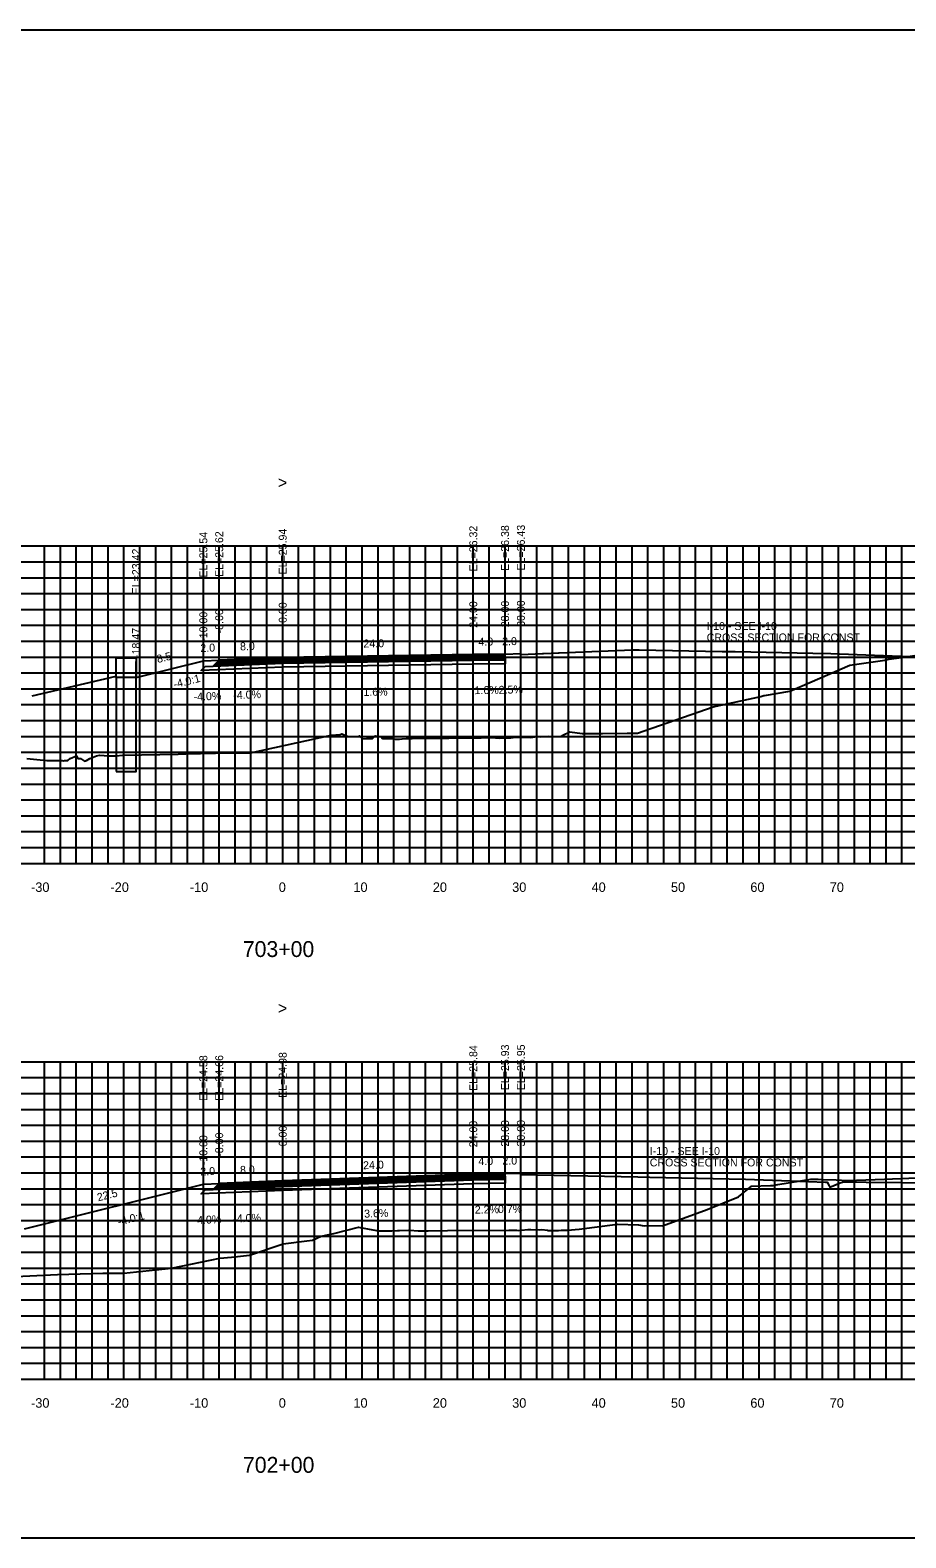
# Model space of a CAD drawing. Extents: x 1797518 to 1804843, y 248068 to 251132.
# Drawn here: x 1802599.2 to 1802709.5, y 250079.4 to 250269.4 of the extents above; entities that cross this region are included whole.
import ezdxf

# ---------------------------------------------------------------- set-up
doc = ezdxf.new("R2010")
doc.units = 0
for name, color, linetype in [('1', 7, 'Continuous'), ('10', 7, 'Continuous'), ('3', 7, 'Continuous'), ('4', 7, 'Continuous'), ('60', 7, 'Continuous'), ('BASE', 7, 'Continuous'), ('CL-CNST', 7, 'Continuous'), ('Level 62', 7, 'Continuous'), ('LOWER BINDER', 7, 'Continuous'), ('M-ROADS', 7, 'Continuous'), ('UPPER BINDER', 7, 'Continuous'), ('WEARING', 7, 'Continuous')]:
    doc.layers.add(name, color=color, linetype=linetype)

msp = doc.modelspace()

# ---------------------------------------------------------------- linework, layer by layer
for p, q in [((1802623, 250190.05), (1802623, 250192.05)), ((1802631, 250190.37), (1802631, 250192.37)), ((1802655, 250190.75), (1802655, 250192.75)), ((1802659, 250190.81), (1802659, 250192.81)), ((1802661, 250190.86), (1802661, 250192.86)), ((1802621, 250189.97), (1802621, 250191.97)), ((1802612.53, 250187.85), (1802612.53, 250189.85)), ((1802621, 250124.01), (1802621, 250126.01)), ((1802623, 250124.09), (1802623, 250126.09)), ((1802631, 250124.41), (1802631, 250126.41)), ((1802655, 250125.28), (1802655, 250127.28)), ((1802659, 250125.36), (1802659, 250127.36)), ((1802661, 250125.38), (1802661, 250127.38))]:
    msp.add_line(p, q)
msp.add_lwpolyline([(1802481, 250079.43), (1802781, 250079.43), (1802781, 250269.43), (1802481, 250269.43)], close=True)
at = {"layer": '3'}
msp.add_line((1802599.44, 250185.53), (1802610.03, 250188.01), dxfattribs=at)
at = {"layer": '60'}
for p, q in [((1802481, 250164.43), (1802781, 250164.43)), ((1802601, 250164.37), (1802601, 250164.43)), ((1802611, 250164.37), (1802611, 250164.43)), ((1802621, 250164.37), (1802621, 250164.43)), ((1802631, 250164.37), (1802631, 250164.43)), ((1802641, 250164.37), (1802641, 250164.43)), ((1802651, 250164.37), (1802651, 250164.43)), ((1802661, 250164.37), (1802661, 250164.43)), ((1802671, 250164.37), (1802671, 250164.43)), ((1802681, 250164.37), (1802681, 250164.43)), ((1802691, 250164.37), (1802691, 250164.43)), ((1802701, 250164.37), (1802701, 250164.43)), ((1802481, 250099.43), (1802781, 250099.43)), ((1802601, 250099.37), (1802601, 250099.43)), ((1802611, 250099.37), (1802611, 250099.43)), ((1802621, 250099.37), (1802621, 250099.43)), ((1802631, 250099.37), (1802631, 250099.43)), ((1802641, 250099.37), (1802641, 250099.43)), ((1802651, 250099.37), (1802651, 250099.43)), ((1802661, 250099.37), (1802661, 250099.43)), ((1802671, 250099.37), (1802671, 250099.43)), ((1802681, 250099.37), (1802681, 250099.43)), ((1802691, 250099.37), (1802691, 250099.43)), ((1802701, 250099.37), (1802701, 250099.43))]:
    msp.add_line(p, q, dxfattribs=at)
at = {"layer": 'BASE'}
for points in [[(1802621.25, 250189.26), (1802622.25, 250189.3), (1802631, 250189.65), (1802655, 250190.03), (1802659, 250190.09), (1802659, 250189.59), (1802655, 250189.53), (1802631, 250189.15), (1802620.73, 250188.74)], [(1802621.25, 250123.3), (1802622.25, 250123.34), (1802631, 250123.69), (1802655, 250124.56), (1802659, 250124.64), (1802659, 250124.14), (1802655, 250124.06), (1802631, 250123.19), (1802620.73, 250122.78)]]:
    msp.add_lwpolyline(points, close=True, dxfattribs=at)
at = {"layer": 'CL-CNST'}
for points in [[(1802612.53, 250187.85), (1802610.03, 250187.85), (1802610.03, 250190.35), (1802612.53, 250190.35)], [(1802610.03, 250175.99), (1802612.53, 250175.99), (1802612.53, 250187.85), (1802610.03, 250187.85)]]:
    msp.add_lwpolyline(points, close=True, dxfattribs=at)
for points in [[(1802612.53, 250187.85), (1802621, 250189.97), (1802623, 250190.05), (1802631, 250190.37), (1802655, 250190.75), (1802659, 250190.81), (1802661, 250190.86)], [(1802661, 250190.75), (1802663.71, 250190.86), (1802663.83, 250190.87), (1802665.75, 250190.95), (1802665.84, 250190.95), (1802675.04, 250191.33), (1802675.91, 250191.36), (1802686.34, 250191.15), (1802687.99, 250191.12), (1802697.79, 250190.92), (1802700.06, 250190.87), (1802707.78, 250190.58), (1802710.13, 250190.49)], [(1802598.49, 250118.38), (1802621, 250124.01), (1802623, 250124.09), (1802631, 250124.41), (1802655, 250125.28), (1802659, 250125.36), (1802661, 250125.38)], [(1802661, 250125.23), (1802675.73, 250124.92), (1802677.24, 250124.89), (1802687.23, 250124.69), (1802689.31, 250124.64), (1802697.22, 250124.34), (1802699.36, 250124.26), (1802699.53, 250124.25), (1802699.58, 250124.25), (1802699.83, 250123.78), (1802699.9, 250123.64), (1802701.23, 250124.15), (1802701.62, 250124.3), (1802704.47, 250124.27), (1802713.39, 250124.19)]]:
    msp.add_lwpolyline(points, dxfattribs=at)
at = {"layer": 'Level 62'}
for p, q in [((1802481, 250204.43), (1802781, 250204.43)), ((1802601, 250164.43), (1802601, 250204.43)), ((1802603, 250164.43), (1802603, 250204.43)), ((1802605, 250164.43), (1802605, 250204.43)), ((1802607, 250164.43), (1802607, 250204.43)), ((1802609, 250164.43), (1802609, 250204.43)), ((1802611, 250164.43), (1802611, 250204.43)), ((1802613, 250164.43), (1802613, 250204.43)), ((1802615, 250164.43), (1802615, 250204.43)), ((1802617, 250164.43), (1802617, 250204.43)), ((1802619, 250164.43), (1802619, 250204.43)), ((1802621, 250164.43), (1802621, 250204.43)), ((1802623, 250164.43), (1802623, 250204.43)), ((1802625, 250164.43), (1802625, 250204.43)), ((1802627, 250164.43), (1802627, 250204.43)), ((1802629, 250164.43), (1802629, 250204.43)), ((1802631, 250164.43), (1802631, 250204.43)), ((1802633, 250164.43), (1802633, 250204.43)), ((1802635, 250164.43), (1802635, 250204.43)), ((1802637, 250164.43), (1802637, 250204.43)), ((1802639, 250164.43), (1802639, 250204.43)), ((1802641, 250164.43), (1802641, 250204.43)), ((1802643, 250164.43), (1802643, 250204.43)), ((1802645, 250164.43), (1802645, 250204.43)), ((1802647, 250164.43), (1802647, 250204.43)), ((1802649, 250164.43), (1802649, 250204.43)), ((1802651, 250164.43), (1802651, 250204.43)), ((1802653, 250164.43), (1802653, 250204.43)), ((1802655, 250164.43), (1802655, 250204.43)), ((1802657, 250164.43), (1802657, 250204.43)), ((1802659, 250164.43), (1802659, 250204.43)), ((1802661, 250164.43), (1802661, 250204.43)), ((1802663, 250164.43), (1802663, 250204.43)), ((1802665, 250164.43), (1802665, 250204.43)), ((1802667, 250164.43), (1802667, 250204.43)), ((1802669, 250164.43), (1802669, 250204.43)), ((1802671, 250164.43), (1802671, 250204.43)), ((1802673, 250164.43), (1802673, 250204.43)), ((1802675, 250164.43), (1802675, 250204.43)), ((1802677, 250164.43), (1802677, 250204.43)), ((1802679, 250164.43), (1802679, 250204.43)), ((1802681, 250164.43), (1802681, 250204.43)), ((1802683, 250164.43), (1802683, 250204.43)), ((1802685, 250164.43), (1802685, 250204.43)), ((1802687, 250164.43), (1802687, 250204.43)), ((1802689, 250164.43), (1802689, 250204.43)), ((1802691, 250164.43), (1802691, 250204.43)), ((1802693, 250164.43), (1802693, 250204.43)), ((1802695, 250164.43), (1802695, 250204.43)), ((1802697, 250164.43), (1802697, 250204.43)), ((1802699, 250164.43), (1802699, 250204.43)), ((1802701, 250164.43), (1802701, 250204.43)), ((1802703, 250164.43), (1802703, 250204.43)), ((1802705, 250164.43), (1802705, 250204.43)), ((1802707, 250164.43), (1802707, 250204.43)), ((1802709, 250164.43), (1802709, 250204.43)), ((1802481, 250202.43), (1802781, 250202.43)), ((1802481, 250200.43), (1802781, 250200.43)), ((1802481, 250198.43), (1802781, 250198.43)), ((1802481, 250196.43), (1802781, 250196.43)), ((1802481, 250194.43), (1802781, 250194.43)), ((1802481, 250192.43), (1802781, 250192.43)), ((1802481, 250190.43), (1802781, 250190.43)), ((1802481, 250188.43), (1802781, 250188.43)), ((1802481, 250186.43), (1802781, 250186.43)), ((1802481, 250184.43), (1802781, 250184.43)), ((1802481, 250182.43), (1802781, 250182.43)), ((1802481, 250180.43), (1802781, 250180.43)), ((1802481, 250178.43), (1802781, 250178.43)), ((1802481, 250176.43), (1802781, 250176.43)), ((1802481, 250174.43), (1802781, 250174.43)), ((1802481, 250172.43), (1802781, 250172.43)), ((1802481, 250170.43), (1802781, 250170.43)), ((1802481, 250168.43), (1802781, 250168.43)), ((1802481, 250166.43), (1802781, 250166.43)), ((1802481, 250164.43), (1802781, 250164.43)), ((1802481, 250139.43), (1802781, 250139.43)), ((1802601, 250099.43), (1802601, 250139.43)), ((1802603, 250099.43), (1802603, 250139.43)), ((1802605, 250099.43), (1802605, 250139.43)), ((1802607, 250099.43), (1802607, 250139.43)), ((1802609, 250099.43), (1802609, 250139.43)), ((1802611, 250099.43), (1802611, 250139.43)), ((1802613, 250099.43), (1802613, 250139.43)), ((1802615, 250099.43), (1802615, 250139.43)), ((1802617, 250099.43), (1802617, 250139.43)), ((1802619, 250099.43), (1802619, 250139.43)), ((1802621, 250099.43), (1802621, 250139.43)), ((1802623, 250099.43), (1802623, 250139.43)), ((1802625, 250099.43), (1802625, 250139.43)), ((1802627, 250099.43), (1802627, 250139.43)), ((1802629, 250099.43), (1802629, 250139.43)), ((1802631, 250099.43), (1802631, 250139.43)), ((1802633, 250099.43), (1802633, 250139.43)), ((1802635, 250099.43), (1802635, 250139.43)), ((1802637, 250099.43), (1802637, 250139.43)), ((1802639, 250099.43), (1802639, 250139.43)), ((1802641, 250099.43), (1802641, 250139.43)), ((1802643, 250099.43), (1802643, 250139.43)), ((1802645, 250099.43), (1802645, 250139.43)), ((1802647, 250099.43), (1802647, 250139.43)), ((1802649, 250099.43), (1802649, 250139.43)), ((1802651, 250099.43), (1802651, 250139.43)), ((1802653, 250099.43), (1802653, 250139.43)), ((1802655, 250099.43), (1802655, 250139.43)), ((1802657, 250099.43), (1802657, 250139.43)), ((1802659, 250099.43), (1802659, 250139.43)), ((1802661, 250099.43), (1802661, 250139.43)), ((1802663, 250099.43), (1802663, 250139.43)), ((1802665, 250099.43), (1802665, 250139.43)), ((1802667, 250099.43), (1802667, 250139.43)), ((1802669, 250099.43), (1802669, 250139.43)), ((1802671, 250099.43), (1802671, 250139.43)), ((1802673, 250099.43), (1802673, 250139.43)), ((1802675, 250099.43), (1802675, 250139.43)), ((1802677, 250099.43), (1802677, 250139.43)), ((1802679, 250099.43), (1802679, 250139.43)), ((1802681, 250099.43), (1802681, 250139.43)), ((1802683, 250099.43), (1802683, 250139.43)), ((1802685, 250099.43), (1802685, 250139.43)), ((1802687, 250099.43), (1802687, 250139.43)), ((1802689, 250099.43), (1802689, 250139.43)), ((1802691, 250099.43), (1802691, 250139.43)), ((1802693, 250099.43), (1802693, 250139.43)), ((1802695, 250099.43), (1802695, 250139.43)), ((1802697, 250099.43), (1802697, 250139.43)), ((1802699, 250099.43), (1802699, 250139.43)), ((1802701, 250099.43), (1802701, 250139.43)), ((1802703, 250099.43), (1802703, 250139.43)), ((1802705, 250099.43), (1802705, 250139.43)), ((1802707, 250099.43), (1802707, 250139.43)), ((1802709, 250099.43), (1802709, 250139.43)), ((1802481, 250137.43), (1802781, 250137.43)), ((1802481, 250135.43), (1802781, 250135.43)), ((1802481, 250133.43), (1802781, 250133.43)), ((1802481, 250131.43), (1802781, 250131.43)), ((1802481, 250129.43), (1802781, 250129.43)), ((1802481, 250127.43), (1802781, 250127.43)), ((1802481, 250125.43), (1802781, 250125.43)), ((1802481, 250123.43), (1802781, 250123.43)), ((1802481, 250121.43), (1802781, 250121.43)), ((1802481, 250119.43), (1802781, 250119.43)), ((1802481, 250117.43), (1802781, 250117.43)), ((1802481, 250115.43), (1802781, 250115.43)), ((1802481, 250113.43), (1802781, 250113.43)), ((1802481, 250111.43), (1802781, 250111.43)), ((1802481, 250109.43), (1802781, 250109.43)), ((1802481, 250107.43), (1802781, 250107.43)), ((1802481, 250105.43), (1802781, 250105.43)), ((1802481, 250103.43), (1802781, 250103.43)), ((1802481, 250101.43), (1802781, 250101.43)), ((1802481, 250099.43), (1802781, 250099.43))]:
    msp.add_line(p, q, dxfattribs=at)
at = {"layer": 'LOWER BINDER'}
for points in [[(1802631, 250189.84), (1802655, 250190.22), (1802659, 250190.28), (1802659, 250190.09), (1802655, 250190.03), (1802631, 250189.65), (1802622.25, 250189.3), (1802622.45, 250189.5)], [(1802631, 250190.03), (1802655, 250190.41), (1802659, 250190.48), (1802659, 250190.28), (1802655, 250190.22), (1802631, 250189.84), (1802622.45, 250189.5), (1802622.65, 250189.7)], [(1802631, 250123.88), (1802655, 250124.75), (1802659, 250124.83), (1802659, 250124.64), (1802655, 250124.56), (1802631, 250123.69), (1802622.25, 250123.34), (1802622.45, 250123.54)], [(1802631, 250124.07), (1802655, 250124.94), (1802659, 250125.03), (1802659, 250124.83), (1802655, 250124.75), (1802631, 250123.88), (1802622.45, 250123.54), (1802622.65, 250123.73)]]:
    msp.add_lwpolyline(points, close=True, dxfattribs=at)
at = {"layer": 'M-ROADS'}
for points in [[(1802598.77, 250177.64), (1802601.27, 250177.4), (1802603.22, 250177.38), (1802603.38, 250177.36), (1802603.51, 250177.38), (1802603.94, 250177.4), (1802604.21, 250177.66), (1802605.02, 250177.99), (1802605.18, 250177.65), (1802605.53, 250177.66), (1802606.04, 250177.33), (1802606.27, 250177.4), (1802606.71, 250177.66), (1802607.53, 250177.99), (1802607.9, 250178.05), (1802609.11, 250177.99), (1802610.03, 250177.99), (1802610.8, 250178.07), (1802613.19, 250178.1), (1802617.81, 250178.21), (1802618.81, 250178.23), (1802624.38, 250178.35), (1802626.06, 250178.38), (1802626.92, 250178.38), (1802637.12, 250180.58), (1802638.23, 250180.69), (1802638.44, 250180.74), (1802639.24, 250180.41), (1802640.48, 250180.41), (1802640.66, 250180.52), (1802641.04, 250180.12), (1802641.56, 250180.16), (1802642.29, 250180.15), (1802642.64, 250180.51), (1802642.98, 250180.41), (1802643.36, 250180.4), (1802643.56, 250180.15), (1802643.95, 250180.17), (1802644.81, 250180.17), (1802645.18, 250180.07), (1802645.71, 250180.07), (1802646.04, 250180.12), (1802646.56, 250180.16), (1802647.29, 250180.15), (1802651.92, 250180.22), (1802656.01, 250180.27), (1802656.79, 250180.29), (1802657.26, 250180.3), (1802658.32, 250180.22), (1802658.46, 250180.24), (1802659.47, 250180.25), (1802659.72, 250180.25), (1802660.37, 250180.33), (1802661, 250180.33), (1802661.74, 250180.35), (1802662.26, 250180.3), (1802662.99, 250180.41), (1802663.49, 250180.39), (1802664.49, 250180.47), (1802666, 250180.43), (1802666.29, 250180.59), (1802667.16, 250180.99), (1802668.7, 250180.8), (1802671.28, 250180.78), (1802674.39, 250180.82), (1802675.68, 250180.85), (1802685.23, 250184.17), (1802691.23, 250185.46), (1802691.6, 250185.59), (1802691.67, 250185.6), (1802694.86, 250186.14), (1802702.44, 250189.4), (1802706.83, 250190.05), (1802707.03, 250190.08), (1802707.28, 250190.17), (1802707.37, 250190.18), (1802708.9, 250190.36), (1802712.93, 250190.98)], [(1802593.87, 250112.2), (1802602.63, 250112.6), (1802608.36, 250112.8), (1802610.45, 250112.79), (1802610.73, 250112.79), (1802611, 250112.79), (1802614.99, 250113.22), (1802617, 250113.43), (1802623.06, 250114.67), (1802624.53, 250114.82), (1802626.82, 250115.06), (1802631.07, 250116.5), (1802634.05, 250116.85), (1802634.77, 250116.94), (1802635.84, 250117.45), (1802637.43, 250117.78), (1802640.53, 250118.59), (1802642.34, 250118.23), (1802643.06, 250118.11), (1802643.37, 250118.13), (1802644.31, 250118.14), (1802644.73, 250118.11), (1802645.46, 250118.17), (1802645.59, 250118.17), (1802645.72, 250118.17), (1802646.84, 250118.19), (1802647.02, 250118.19), (1802648.06, 250118.11), (1802648.37, 250118.13), (1802649.31, 250118.14), (1802651.75, 250118.15), (1802659.5, 250118.21), (1802660.48, 250118.19), (1802660.75, 250118.18), (1802661.08, 250118.19), (1802661.86, 250118.27), (1802662.07, 250118.27), (1802662.27, 250118.27), (1802663.31, 250118.25), (1802663.62, 250118.27), (1802664.36, 250118.22), (1802664.44, 250118.17), (1802665.09, 250118.16), (1802665.75, 250118.18), (1802666.07, 250118.19), (1802666.86, 250118.2), (1802668.32, 250118.33), (1802673.17, 250118.98), (1802675.82, 250118.87), (1802676.52, 250118.77), (1802676.9, 250118.78), (1802678.82, 250118.75), (1802684.45, 250120.83), (1802688.39, 250122.39), (1802690.04, 250123.75), (1802692.45, 250123.85), (1802692.62, 250123.85), (1802692.78, 250123.85), (1802693.38, 250123.97), (1802697.53, 250124.65), (1802698.44, 250124.63), (1802698.91, 250124.61), (1802700.73, 250124.53), (1802702.09, 250124.47), (1802706.81, 250124.64), (1802710.86, 250124.79)]]:
    msp.add_lwpolyline(points, dxfattribs=at)
at = {"layer": 'UPPER BINDER'}
for points in [[(1802659, 250190.48), (1802659, 250190.66), (1802655, 250190.6), (1802631, 250190.22), (1802622.85, 250189.89), (1802622.65, 250189.7), (1802631, 250190.03), (1802655, 250190.41)], [(1802659, 250125.03), (1802659, 250125.21), (1802655, 250125.13), (1802631, 250124.26), (1802622.85, 250123.93), (1802622.65, 250123.73), (1802631, 250124.07), (1802655, 250124.94)]]:
    msp.add_lwpolyline(points, close=True, dxfattribs=at)
at = {"layer": 'WEARING'}
for points in [[(1802659, 250190.66), (1802659, 250190.81), (1802655, 250190.75), (1802631, 250190.37), (1802623, 250190.05), (1802622.85, 250189.89), (1802631, 250190.22), (1802655, 250190.6)], [(1802659, 250125.21), (1802659, 250125.36), (1802655, 250125.28), (1802631, 250124.41), (1802623, 250124.09), (1802622.85, 250123.93), (1802631, 250124.26), (1802655, 250125.13)]]:
    msp.add_lwpolyline(points, close=True, dxfattribs=at)

# ---------------------------------------------------------------- texts
for p in [(1802617.37, 250186.49), (1802610.35, 250118.77)]:
    msp.add_text('-4.0:1', height=1, rotation=14.0362).set_placement(p)
at = {"layer": '1'}
for s, p in [('703+00', (1802625.97, 250152.63)), ('702+00', (1802625.99, 250087.63))]:
    msp.add_text(s, height=2, dxfattribs=at).set_placement(p)
at = {"layer": '10'}
for s, p in [('-30', (1802599.3, 250160.83)), ('-20', (1802609.3, 250160.83)), ('-10', (1802619.3, 250160.83)), ('0', (1802630.5, 250160.83)), ('10', (1802639.9, 250160.83)), ('20', (1802649.9, 250160.83)), ('30', (1802659.9, 250160.83)), ('40', (1802669.9, 250160.83)), ('50', (1802679.9, 250160.83)), ('60', (1802689.9, 250160.83)), ('70', (1802699.9, 250160.83)), ('-30', (1802599.3, 250095.83)), ('-20', (1802609.3, 250095.83)), ('-10', (1802619.3, 250095.83)), ('0', (1802630.5, 250095.83)), ('10', (1802639.9, 250095.83)), ('20', (1802649.9, 250095.83)), ('30', (1802659.9, 250095.83)), ('40', (1802669.9, 250095.83)), ('50', (1802679.9, 250095.83)), ('60', (1802689.9, 250095.83)), ('70', (1802699.9, 250095.83))]:
    msp.add_text(s, height=1.2, dxfattribs=at).set_placement(p)
at = {"layer": '3'}
for s, p in [('EL=25.54', (1802621.5, 250200.44)), ('EL=25.62', (1802623.5, 250200.52)), ('EL=25.94', (1802631.5, 250200.84)), ('EL=26.32', (1802655.5, 250201.22)), ('EL=26.38', (1802659.5, 250201.28)), ('EL=26.43', (1802661.5, 250201.33)), ('EL=23.42', (1802613.03, 250198.33)), ('-10.00', (1802621.5, 250192.35)), ('-8.00', (1802623.5, 250193.42)), ('0.00', (1802631.5, 250194.73)), ('24.00', (1802655.5, 250194.12)), ('28.00', (1802659.5, 250194.18)), ('30.00', (1802661.5, 250194.23)), ('-18.47', (1802613.03, 250190.31)), ('EL=25.84', (1802655.5, 250135.75)), ('EL=25.93', (1802659.5, 250135.84)), ('EL=25.95', (1802661.5, 250135.85)), ('EL=24.58', (1802621.5, 250134.48)), ('EL=24.66', (1802623.5, 250134.51)), ('EL=24.98', (1802631.5, 250134.88)), ('0.00', (1802631.5, 250128.77)), ('24.00', (1802655.5, 250128.65)), ('28.00', (1802659.5, 250128.73)), ('30.00', (1802661.5, 250128.75)), ('-10.00', (1802621.5, 250126.39)), ('-8.00', (1802623.5, 250127.46))]:
    msp.add_text(s, height=1, rotation=90, dxfattribs=at).set_placement(p)
for s, p in [('I-10 - SEE I-10', (1802684.4, 250193.84)), ('CROSS SECTION FOR CONST ', (1802684.4, 250192.4)), ('I-10 - SEE I-10', (1802677.23, 250127.68)), ('CROSS SECTION FOR CONST ', (1802677.23, 250126.24))]:
    msp.add_text(s, height=1, dxfattribs=at).set_placement(p)
at = {"layer": '4'}
for s, rotation, p in [('2.0', 2.2906, (1802620.64, 250191.06)), ('8.0', 2.2906, (1802625.64, 250191.26)), ('24.0', 0.9044, (1802641.17, 250191.63)), ('4.0', 0.9044, (1802655.66, 250191.86)), ('2.0', 1.4314, (1802658.65, 250191.9)), ('8.5', 14.0362, (1802615.26, 250189.67)), ('1.6%', 0.9044, (1802641.17, 250185.53)), ('1.6%', 0.9044, (1802655.17, 250185.75)), ('2.5%', 1.4314, (1802658.21, 250185.79)), ('-4.0%', 2.2906, (1802619.79, 250184.92)), ('-4.0%', 2.2906, (1802624.79, 250185.12)), ('4.0', 1.2603, (1802655.65, 250126.39)), ('2.0', 0.3812, (1802658.67, 250126.46)), ('2.0', 2.2906, (1802620.64, 250125.09)), ('8.0', 2.2906, (1802625.64, 250125.29)), ('24.0', 2.0715, (1802641.14, 250125.88)), ('22.5', 14.0362, (1802607.75, 250121.83)), ('-4.0%', 2.2906, (1802619.79, 250118.96)), ('-4.0%', 2.2906, (1802624.79, 250119.16)), ('3.6%', 2.0715, (1802641.27, 250119.78)), ('2.2%', 1.2603, (1802655.2, 250120.28)), ('0.7%', 0.3812, (1802658.12, 250120.36))]:
    msp.add_text(s, height=1, rotation=rotation, dxfattribs=at).set_placement(p)
at = {"layer": '60'}
for p in [(1802630.39, 250211.68), (1802630.39, 250145.44)]:
    msp.add_text('>', height=1.5, dxfattribs=at).set_placement(p)

doc.saveas('drawing.dxf')
